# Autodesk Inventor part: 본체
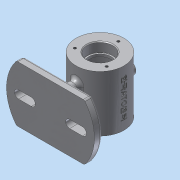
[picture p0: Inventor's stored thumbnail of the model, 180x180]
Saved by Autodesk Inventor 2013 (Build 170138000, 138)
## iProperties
Created: 2017-12
Part Number: 본체
Material: 알루미늄 6061
Document SubType Name: Modeling
Designer: Administrator
Density: 2.71 g/cm^3
Mass: 467.681 g
Surface Area: 486.49 cm^2
Volume: 172.576 cm^3
Author: Administrator
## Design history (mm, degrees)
sketch "스케치1"
  geometry: C1 r 30 at (0, 0); 1 further point
  constraints: 1 centre point, 1 coincident
  dimensions: "d0" = 60 diameter of C1
extrude "돌출1" new body sketch "스케치1" stored distance "d2" = 70; taper "d3" = 0 deg
sketch "스케치2"
  geometry: L1 (30, -35)-(-30, -35) reference; L2 (-30, -35)-(-30, 35) reference; L3 (-30, 35)-(30, 35) reference; L4 (30, 35)-(30, -35) reference; L5 (0, 35)-(0, 0); L6 (16, 35)-(16, 23); L7 (16, 23)-(14, 23); L8 (14, 23)-(14, 20); L9 (14, 20)-(25, 20); L10 (25, 20)-(25, 0); L11 (25, 0)-(0, 0); L12 (16, 35)-(-0.423, 35)
  constraints: 16 end point, 5 parallel, 3 point on line, 1 midpoint, 1 perpendicular
  dimensions: "d4" = 50 diameter of L10 L5; "d6" = 32 diameter of L6 L5; "d7" = 28 diameter of L8 L5; "d8" = 12 distance between parallel lines of L7 L3; "d9" = 3 distance between parallel lines of L9 L7
revolve "회전1" sketch "스케치2" stored, may be unused: angle "d10" = 90 deg
sketch "스케치4"
  geometry: L1 (0, 0)-(-33.046, -19.079); L2 (0, 0)-(33.646, -19.426); L3 (0, 0)-(0, 23); C1 r 16 at (0, 0) reference; C2 r 30 at (0, 0) reference; A1 r 23 centre (0, 0) between (0, 23) and (-19.919, -11.5); 1 further point
  constraints: 6 end point, 3 point on circle, 2 point on line, 1 centre point, 1 coincident, 1 vertical, 1 vertical alignment
  dimensions: "d11" = 46 diameter of A1; "d13" = 120 deg angle of L2 L3; "d15" = 120 deg angle of L3 L1
hole "구멍1" sketch "스케치4" at (0, 23), (-19.919, -11.5), (19.919, -11.5) diameter "d17" = 3.242; stored, may be unused: countersink angle "d21" = 90 deg, drill point angle "d23" = 118 deg; dims "d18" = 8, "d19" = 4, "d20" = 2, "d22" = 10
fillet "모깎기1" dims "d24" = 3
chamfer "모따기1" distance "d25" = 1; stored, may be unused: second distance "d26" = 2, angle "d27" = 45 deg
fillet "모깎기2" dims "d28" = 0.3
sketch "스케치5"
  geometry: 1 further point
node "작업 평면2"
sketch "스케치6"
  geometry: C1 r 8 at (0, 0); 1 further point
  constraints: 1 centre point, 1 coincident
  dimensions: "d30" = 16 diameter of C1
extrude "돌출2" join sketch "스케치6" stored distance "d32" = 70; taper "d33" = 0 deg
sketch "스케치8"
  geometry: C1 r 8 at (0, 0) reference; C2 r 4 at (0, 0)
  constraints: 1 centre point, 1 coincident
  dimensions: "d34" = 8 diameter of C2
extrude "돌출3" cut sketch "스케치8" distance "d36" = 30; taper "d37" = 0 deg
chamfer "모따기2" distance "d38" = 1; stored, may be unused: second distance "d39" = 2, angle "d40" = 45 deg
fillet "모깎기3" dims "d41" = 3
sketch "스케치9"
  geometry: 1 further point
node "작업 평면3"
sketch "스케치10"
  geometry: L1 (-42.426, 35)-(42.426, 35); L2 (-42.426, -35)-(42.426, -35); A1 r 55 centre (0, 0) between (-42.426, 35) and (-42.426, -35); A2 r 55 centre (0, 0) between (42.426, -35) and (42.426, 35); 1 further point
  constraints: 4 end point, 4 point on circle, 2 centre point, 1 coincident, 1 horizontal, 1 parallel
  dimensions: "d47" = 35 vertical distance of L1.end point (0, 0); "d48" = 35 vertical distance of L2.end point (0, 0); "d49" = 55 radius of A1; "d50" = 55 radius of A2
extrude "돌출4" join sketch "스케치10" distance "d51" = 10; taper "d52" = 0 deg
sketch "스케치11"
  geometry: L1 (42.426, 35)-(-42.426, 35) reference; L2 (-40, -5)-(-24, -5); L3 (-40, 5)-(-24, 5); L4 (-42.426, 35)-(42.426, 35) reference; L5 (42.426, -35)-(-42.426, -35) reference; A1 r 55 centre (0, 0) between (42.426, -35) and (42.426, 35) reference; A2 r 5 centre (-40, 0) between (-40, 5) and (-40, -5); A3 r 5 centre (-24, 0) between (-24, -5) and (-24, 5); A4 r 55 centre (0, 0) between (-42.426, 35) and (-42.426, -35) reference; A5 r 55 centre (0, 0) between (42.426, -35) and (42.426, 35) reference
  constraints: 4 end point, 4 point on circle, 4 tangent, 2 centre point, 2 parallel, 1 horizontal alignment
  dimensions: "d53" = 5 radius of A2; "d56" = 16 distance of A3.centre A2.centre; "d57" = 24 distance of A1.centre A3.centre
extrude "돌출5" cut sketch "스케치11" distance "d58" = 10; taper "d59" = 0 deg
fillet "모깎기4" dims "d60" = 3
sketch "스케치12"
  geometry: L1 (-40, 5)-(-24, 5) reference; L2 (-5, 15)-(-5, -15); L3 (5, -15)-(5, 15); A1 r 55 centre (0, 0) between (43.352, -33.846) and (43.352, 33.846) reference; A2 r 5 centre (0, -15) between (-5, -15) and (5, -15); A3 r 5 centre (0, 15) between (5, 15) and (-5, 15)
  constraints: 4 end point, 4 point on circle, 4 tangent, 2 centre point, 1 parallel, 1 perpendicular, 1 vertical alignment
  dimensions: "d61" = 30 distance of A3.centre A2.centre; "d63" = 5 radius of A2; "d64" = 15 distance of A3.centre A1.centre
extrude "돌출6" join sketch "스케치12" stored distance "d65" = 10; taper "d66" = 0 deg
fillet "모깎기5" dims "d67" = 5
node "작업 평면5"
sketch "스케치13"
  geometry: L1 (30, 35)-(-30, 35) reference; L2 (30, -35)-(30, 35) reference; 2 further points
  constraints: 1 other
  dimensions: "d69" = 35 distance from line of L1 point (0, 0); "d70" = 30 distance from line of L2 point (0, 0)
feature "엠보싱1" sketch "스케치13" dims "d71" = 0.5, "d72" = 0
node "솔리드1"
mirror "대칭1"
mirror "대칭2"
mirror "대칭3"
node "작업 평면1"
node "작업 평면4"
node "절단 모서리 투영1"
node "절단 모서리 투영2"
other parameters: "d29" = 37, "d42" = -62, "d68" = 83.75
